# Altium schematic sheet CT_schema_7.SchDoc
size 372 x 245 mm
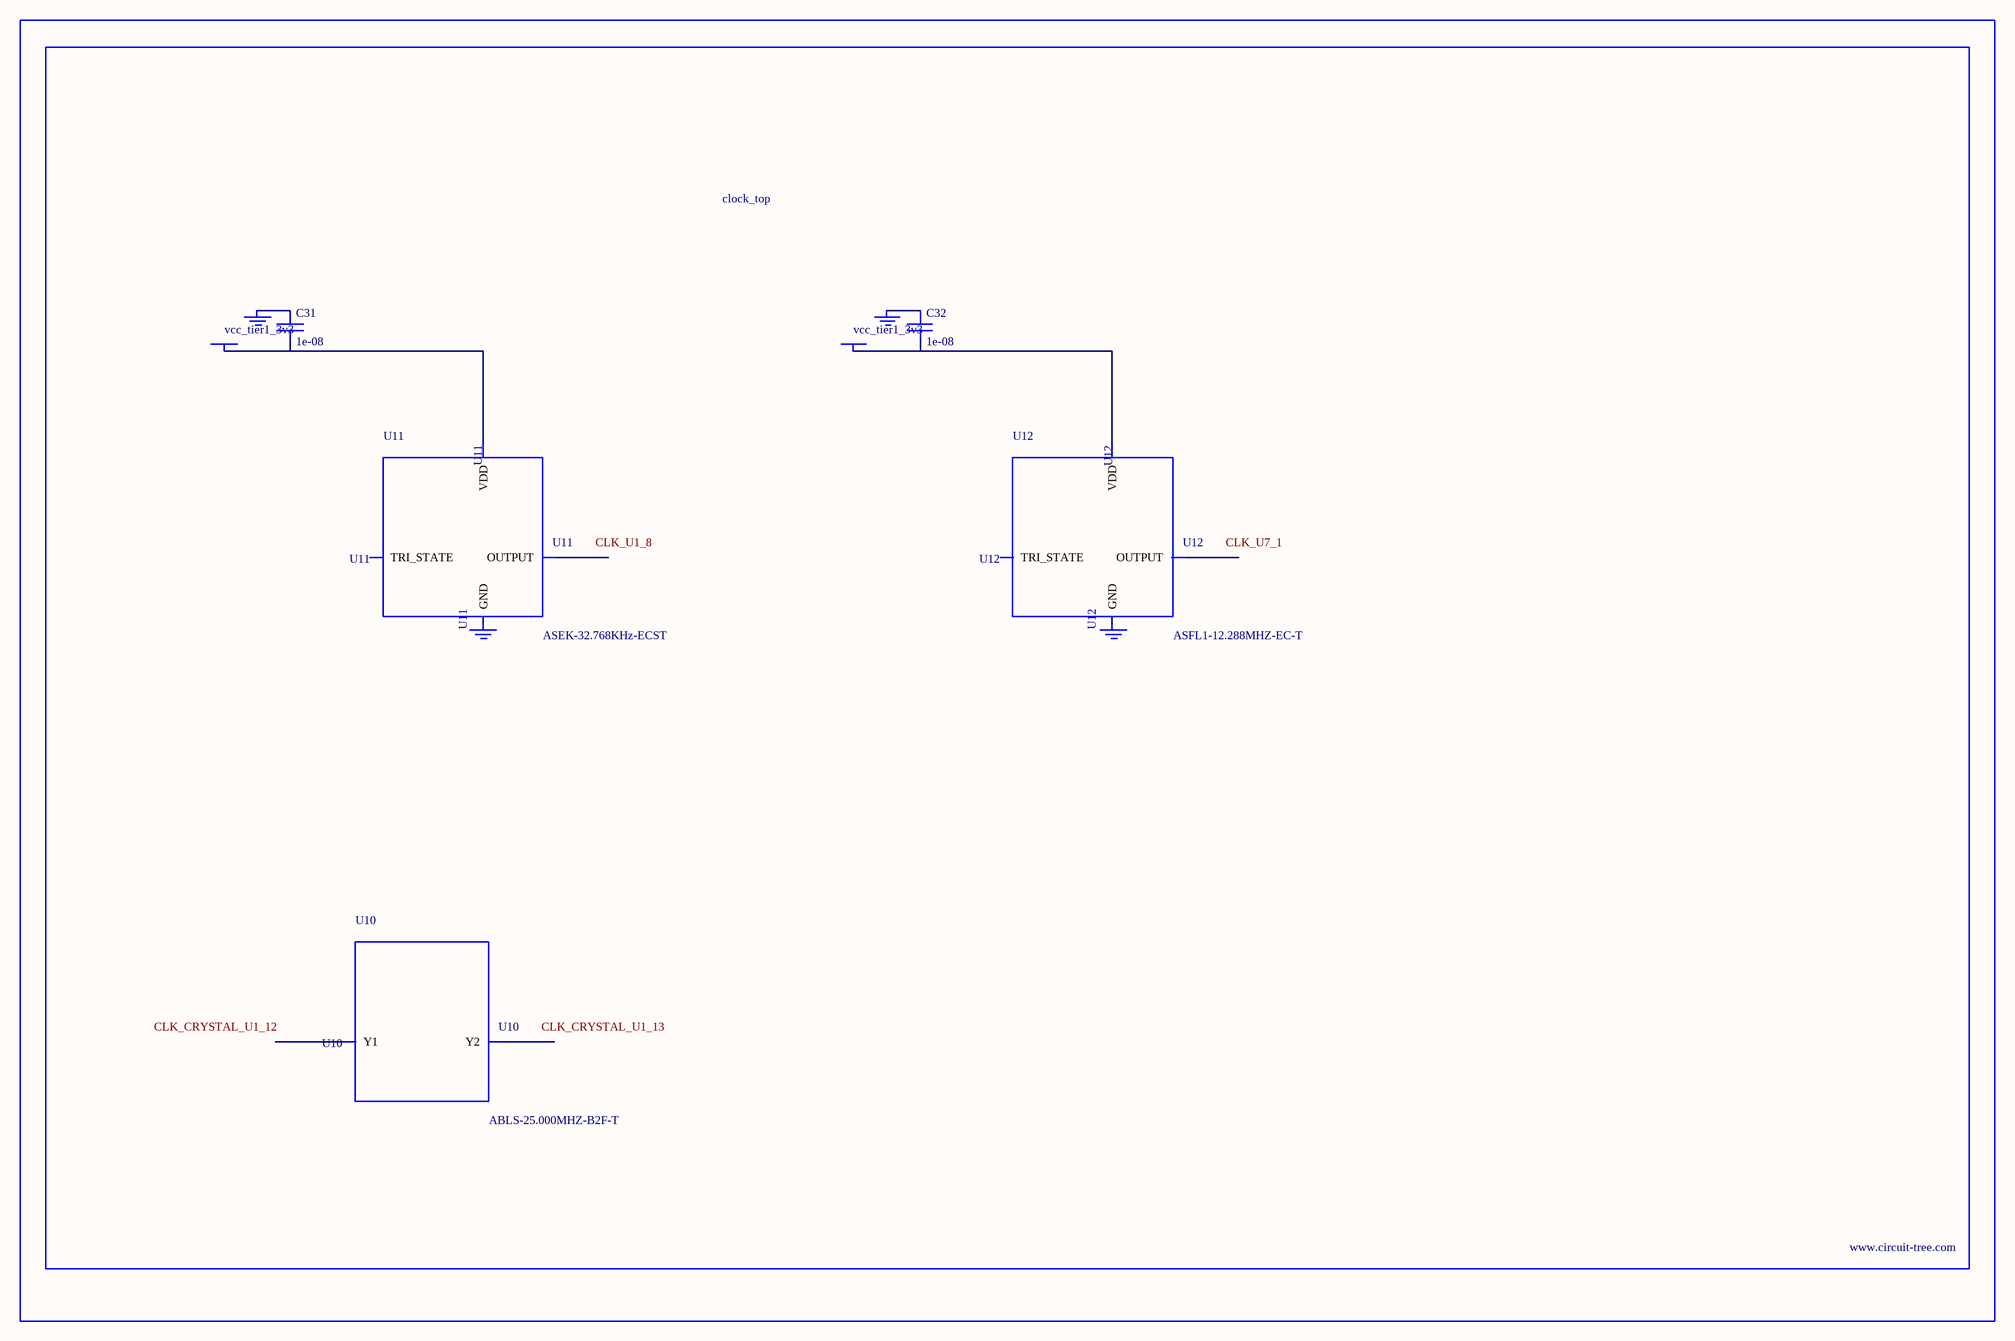
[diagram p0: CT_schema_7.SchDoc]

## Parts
BORDER6  (no value)
C31  1e-08  [C0402]
C32  1e-08  [C0402]
GND_INSTANCE_6_0  (no value)
GND_INSTANCE_6_1  (no value)
GND_INSTANCE_6_2  (no value)
GND_INSTANCE_6_3  (no value)
POWER_INSTANCE_6_0  vcc_tier1_3v3
POWER_INSTANCE_6_1  vcc_tier1_3v3
U10  ABLS-25.000MHZ-B2F-T  [ABLS-25.000MHZ-B2F-T]
U11  ASEK-32.768KHz-ECST  [ASEK]
U12  ASFL1-12.288MHZ-EC-T  [ASFL1]

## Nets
NetC31_1: C31.1 GND_INSTANCE_6_0.0(GND)
NetC31_2: C31.2 POWER_INSTANCE_6_0.0(PWR) U11.4(VDD)
NetC32_1: C32.1 GND_INSTANCE_6_2.0(GND)
NetC32_2: C32.2 POWER_INSTANCE_6_1.0(PWR) U12.4(VDD)

Not connected (* = marked no-connect by the designer): GND_INSTANCE_6_1 0(GND); GND_INSTANCE_6_3 0(GND); U10 1(Y1) 2(Y2); U11 1(TRI_STATE) 2(GND) 3(OUTPUT); U12 1(TRI_STATE) 2(GND) 3(OUTPUT)

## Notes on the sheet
- Labels drawn without touching a wire or pin: CLK_CRYSTAL_U1_12, CLK_CRYSTAL_U1_13, CLK_U1_8, CLK_U7_1

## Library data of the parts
BORDER6 = BORDER_PAGE6
C31 C32 = C0402C103K3RAC
GND_INSTANCE_6_0-GND_INSTANCE_6_3 = GND
POWER_INSTANCE_6_0 POWER_INSTANCE_6_1 = PWR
